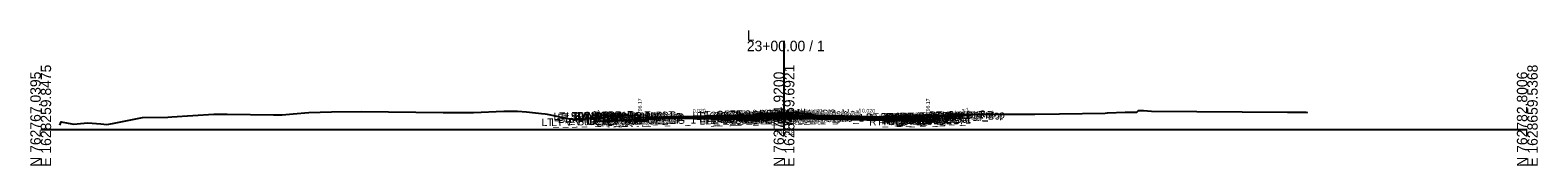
# Model space of a CAD drawing. Extents: x -26 to 4403, y -510 to 9556.
# Drawn here: x 997.2 to 1402.8, y 2990.3 to 3026.7 of the extents above; entities that cross this region are included whole.
import ezdxf

# ---------------------------------------------------------------- set-up
doc = ezdxf.new("R2010")
doc.units = 0
for name, color, linetype in [('Default', 7, 'Continuous'), ('Exist CMT Pavement', 7, 'Continuous'), ('Exist Cross Section Cell', 7, 'Continuous'), ('Exist XS Center Line Elevation Label', 7, 'Continuous'), ('Exist XS Ground Line', 7, 'Continuous'), ('Prop CMT Conc Surface', 7, 'Continuous'), ('Prop CMT Concrete Structures', 7, 'Continuous'), ('Prop CMT Pvmt Course 1', 7, 'Continuous'), ('Prop CMT Pvmt Course 1 CG', 7, 'Continuous'), ('Prop CMT Pvmt Course 2', 7, 'Continuous'), ('Prop CMT Pvmt Course 2 Wedge', 7, 'Continuous'), ('Prop CMT Pvmt Course 3', 7, 'Continuous'), ('Prop CMT Pvmt Course 3 Wedge', 7, 'Continuous'), ('Prop CMT Pvmt Surface', 7, 'Continuous'), ('Prop CMT Slope Grass', 7, 'Continuous'), ('Prop CMT Subgrade Earthwork', 7, 'Continuous'), ('Prop XS Hydro Elevations', 7, 'Continuous'), ('Prop XS SE Text', 7, 'Continuous'), ('Prop XS Side Slope Text', 7, 'Continuous'), ('Scratch_Level_0', 7, 'Continuous')]:
    doc.layers.add(name, color=color, linetype=linetype)

msp = doc.modelspace()

# ---------------------------------------------------------------- linework, layer by layer
at = {"layer": 'Exist CMT Pavement'}
msp.add_lwpolyline([(1163.23, 3002.78), (1167.94, 3002.97), (1171.5, 3003.11), (1176.96, 3002.96), (1190.67, 3002.61)], dxfattribs=at)
at = {"layer": 'Exist Cross Section Cell'}
for p, q in [((1200, 3000), (1200, 3023.91)), ((1000, 3000), (1200, 3000)), ((1200, 3000), (1400, 3000))]:
    msp.add_line(p, q, dxfattribs=at)
at = {"layer": 'Exist XS Ground Line'}
msp.add_lwpolyline([(1005.13, 3001.2), (1005.47, 3002.08), (1007.39, 3001.74), (1008.91, 3001.48), (1010.71, 3001.63), (1012.71, 3001.81), (1016.18, 3001.52), (1017.81, 3001.39), (1019.31, 3001.69), (1027.39, 3003.24), (1034.17, 3003.34), (1035.31, 3003.4), (1046.6, 3004.16), (1047.27, 3004.19), (1050.16, 3004.15), (1062.63, 3003.97), (1063.66, 3003.99), (1065.01, 3004.01), (1067.9, 3004.23), (1072.11, 3004.63), (1078.26, 3004.82), (1086.21, 3004.9), (1108.33, 3004.63), (1116.42, 3004.58), (1124.59, 3004.97), (1126.94, 3004.97), (1128.26, 3005), (1130.7, 3004.79), (1134.76, 3004.35), (1135.7, 3004.24), (1136.25, 3004.14), (1142.27, 3002.91), (1145.44, 3002.8), (1148.47, 3003.04), (1149.3, 3002.63), (1149.83, 3002.26), (1167.94, 3002.97), (1171.5, 3003.11), (1176.96, 3002.96), (1190.69, 3002.61), (1192.06, 3002.44), (1192.57, 3002.38), (1193.22, 3002.83), (1194.25, 3002.87), (1198.26, 3003.09), (1200, 3003.18), (1203.83, 3003.38), (1206.27, 3003.51), (1215.49, 3003.32), (1217.19, 3003.29), (1218.43, 3003.32), (1239.09, 3003.8), (1239.4, 3003.81), (1240.76, 3003.84), (1244.36, 3003.94), (1251.34, 3004.13), (1255.06, 3004.17), (1267.53, 3004.15), (1274.09, 3004.22), (1286.38, 3004.45), (1287.01, 3004.54), (1291.81, 3004.69), (1294.94, 3004.69), (1295.36, 3005.19), (1296.72, 3005.15), (1298.87, 3005), (1335.51, 3004.67), (1339.75, 3004.66), (1340.37, 3004.68), (1340.86, 3004.65)], dxfattribs=at)
at = {"layer": 'Prop CMT Conc Surface'}
for points in [[(1156.75, 3003.76), (1151.75, 3003.86)], [(1161.23, 3003.17), (1161.23, 3003.67), (1160.73, 3003.67)], [(1163.23, 3003.29), (1161.23, 3003.17)], [(1236.75, 3003.29), (1238.75, 3003.17)], [(1238.75, 3003.17), (1238.75, 3003.67), (1239.25, 3003.67)], [(1243.25, 3003.76), (1248.25, 3003.86)]]:
    msp.add_lwpolyline(points, dxfattribs=at)
at = {"layer": 'Prop CMT Concrete Structures'}
for p, q in [((1192.76, 3004.28), (1200, 3004.64)), ((1207.24, 3004.28), (1200, 3004.64)), ((1200, 3004.03), (1208, 3003.87))]:
    msp.add_line(p, q, dxfattribs=at)
for points in [[(1151.75, 3003.53), (1151.75, 3003.86)], [(1151.75, 3003.86), (1156.75, 3003.76)], [(1156.75, 3003.43), (1151.75, 3003.53)], [(1156.75, 3003.76), (1156.75, 3003.43)], [(1163.23, 3003.29), (1161.23, 3003.17), (1161.23, 3003.67), (1160.73, 3003.67)], [(1160.73, 3003.67), (1160.73, 3002.66), (1163.23, 3002.71)], [(1163.23, 3002.71), (1163.23, 3003.29)], [(1192.76, 3004.28), (1192.01, 3004.03), (1192, 3003.87)], [(1192, 3003.87), (1200, 3004.03)], [(1207.24, 3004.28), (1207.99, 3004.03), (1208, 3003.87)], [(1236.75, 3003.29), (1238.75, 3003.17), (1238.75, 3003.67), (1239.25, 3003.67)], [(1239.25, 3003.67), (1239.25, 3002.66), (1236.75, 3002.71)], [(1236.75, 3002.71), (1236.75, 3003.29)], [(1248.25, 3003.86), (1243.25, 3003.76)], [(1243.25, 3003.76), (1243.25, 3003.43)], [(1243.25, 3003.43), (1248.25, 3003.53)], [(1248.25, 3003.53), (1248.25, 3003.86)]]:
    msp.add_lwpolyline(points, dxfattribs=at)
at = {"layer": 'Prop CMT Pvmt Course 1'}
for points in [[(1200, 3004.03), (1163.23, 3003.29)], [(1163.23, 3003.04), (1190.67, 3003.59), (1200, 3003.78)], [(1163.23, 3003.29), (1163.23, 3003.04), (1163.23, 3003.04)], [(1200, 3003.78), (1200, 3004.03)], [(1200, 3004.03), (1236.75, 3003.29)], [(1236.75, 3003.04), (1200, 3003.78)], [(1208.75, 3003.6), (1208.75, 3003.6), (1208.75, 3003.6)], [(1236.75, 3003.29), (1236.75, 3003.04)]]:
    msp.add_lwpolyline(points, dxfattribs=at)
at = {"layer": 'Prop CMT Pvmt Course 1 CG'}
for points in [[(1163.23, 3002.71), (1160.23, 3002.65), (1159.89, 3002.31)], [(1159.89, 3002.31), (1163.23, 3002.38)], [(1163.23, 3002.38), (1163.23, 3002.71)], [(1200, 3003.11), (1191.25, 3002.94)], [(1200, 3003.11), (1200, 3003.45)], [(1206.41, 3002.98), (1208.75, 3002.94)], [(1236.75, 3002.71), (1239.75, 3002.65), (1240.09, 3002.31)], [(1236.75, 3002.38), (1236.75, 3002.71)], [(1240.09, 3002.31), (1236.75, 3002.38)]]:
    msp.add_lwpolyline(points, dxfattribs=at)
at = {"layer": 'Prop CMT Pvmt Course 2'}
for points in [[(1163.23, 3002.71), (1163.23, 3002.71), (1163.23, 3003.04), (1163.23, 3003.04)], [(1163.23, 3003.04), (1163.23, 3002.71)], [(1200, 3003.78), (1190.67, 3003.59)], [(1190.67, 3003.59), (1190.67, 3003.26)], [(1190.67, 3003.26), (1200, 3003.45)], [(1200, 3003.45), (1200, 3003.78)], [(1200, 3003.78), (1236.75, 3003.04)], [(1236.75, 3002.71), (1200, 3003.44)], [(1236.75, 3003.04), (1236.75, 3002.71)]]:
    msp.add_lwpolyline(points, dxfattribs=at)
at = {"layer": 'Prop CMT Pvmt Course 2 Wedge'}
for points in [[(1163.23, 3003.04), (1167.94, 3003.14), (1171.5, 3003.21), (1176.96, 3003.32), (1190.67, 3003.59)], [(1190.67, 3003.26), (1176.96, 3002.98), (1176.51, 3002.98), (1171.5, 3003.11), (1167.94, 3002.97), (1163.23, 3002.78)], [(1163.23, 3002.78), (1163.23, 3003.04)], [(1190.67, 3003.59), (1190.67, 3003.26)]]:
    msp.add_lwpolyline(points, dxfattribs=at)
at = {"layer": 'Prop CMT Pvmt Course 3'}
for points in [[(1163.23, 3002.71), (1163.23, 3002.71), (1163.23, 3002.38), (1163.23, 3002.38)], [(1163.23, 3002.38), (1163.23, 3002.71)], [(1200, 3003.45), (1190.67, 3003.26)], [(1190.67, 3003.26), (1190.67, 3002.92)], [(1190.67, 3002.92), (1191.25, 3002.94)], [(1200, 3003.11), (1200, 3003.45)], [(1200, 3003.44), (1236.75, 3002.71)], [(1236.75, 3002.38), (1200, 3003.11)], [(1236.75, 3002.71), (1236.75, 3002.38)]]:
    msp.add_lwpolyline(points, dxfattribs=at)
at = {"layer": 'Prop CMT Pvmt Course 3 Wedge'}
for points in [[(1176.52, 3002.97), (1176.96, 3002.98)], [(1190.67, 3002.61), (1176.96, 3002.96), (1176.52, 3002.97)], [(1176.96, 3002.98), (1190.67, 3003.26)], [(1190.67, 3003.26), (1190.67, 3002.61)]]:
    msp.add_lwpolyline(points, dxfattribs=at)
at = {"layer": 'Prop CMT Pvmt Surface'}
for points in [[(1200, 3004.03), (1163.23, 3003.29)], [(1200, 3004.03), (1236.75, 3003.29)]]:
    msp.add_lwpolyline(points, dxfattribs=at)
at = {"layer": 'Prop CMT Slope Grass'}
for points in [[(1160.73, 3003.67), (1151.25, 3003.86), (1148.59, 3002.98)], [(1239.25, 3003.67), (1248.75, 3003.86), (1249.4, 3004.08)]]:
    msp.add_lwpolyline(points, dxfattribs=at)
at = {"layer": 'Prop CMT Subgrade Earthwork'}
msp.add_line((1163.23, 3002.38), (1163.23, 3002.71), dxfattribs=at)
for points in [[(1163.23, 3002.38), (1159.89, 3002.31), (1158.48, 3003.72)], [(1163.23, 3002.38), (1163.23, 3002.38)], [(1163.23, 3002.38), (1163.23, 3002.38)], [(1191.25, 3002.94), (1190.67, 3002.92)], [(1190.67, 3002.92), (1190.67, 3002.61)], [(1200, 3003.11), (1191.25, 3002.94)], [(1200, 3003.11), (1200, 3003.11)], [(1200, 3003.11), (1208.75, 3002.94)], [(1208.75, 3002.94), (1236.75, 3002.38)], [(1208.75, 3002.94), (1208.75, 3002.94)], [(1208.75, 3002.94), (1208.75, 3002.94)], [(1236.75, 3002.38), (1240.09, 3002.31), (1241.5, 3003.72)], [(1236.75, 3002.38), (1236.75, 3002.38)]]:
    msp.add_lwpolyline(points, dxfattribs=at)

# ---------------------------------------------------------------- texts
at = {"layer": 'Default'}
msp.add_text('-', height=0.0001, dxfattribs=at).set_placement((1000, 3000))
at = {"layer": 'Exist Cross Section Cell'}
for s, p in [('L', (1190, 3023.91)), ('23+00.00 / 1', (1190, 3021.11))]:
    msp.add_text(s, height=2.8, dxfattribs=at).set_placement(p)
for s, p in [('N 762767.0395', (1000, 2990)), ('E 1628259.8475', (1002.8, 2990)), ('N 762774.9200', (1200, 2990)), ('E 1628459.6921', (1202.8, 2990)), ('N 762782.8006', (1400, 2990)), ('E 1628659.5368', (1402.8, 2990))]:
    msp.add_text(s, height=2.8, rotation=90, dxfattribs=at).set_placement(p)
at = {"layer": 'Exist XS Center Line Elevation Label'}
msp.add_text('796.18', height=1.2, dxfattribs=at).set_placement((1197.77, 2998.58))
at = {"layer": 'Prop XS Hydro Elevations'}
for p in [(1161.73, 3004.17), (1239.25, 3004.17)]:
    msp.add_text('796.17', height=1, rotation=90, dxfattribs=at).set_placement(p)
at = {"layer": 'Prop XS SE Text'}
for rotation, p in [(1.1448, (1175.47, 3004.54)), (358.8543, (1221.02, 3004.61))]:
    msp.add_text('0.020', height=1, rotation=rotation, dxfattribs=at).set_placement(p)
at = {"layer": 'Prop XS Side Slope Text'}
for rotation, p in [(18.441, (1148.93, 3003.88)), (18.3951, (1248.08, 3004.43))]:
    msp.add_text('3:1', height=1, rotation=rotation, dxfattribs=at).set_placement(p)
at = {"layer": 'Scratch_Level_0'}
for s, p in [('LT_PV_Sub_Tie_Out', (1134.79, 3000.96)), ('LT_PV_OEEOP_EG', (1137.39, 3001.01)), ('LT_SDWK_Out_Top', (1138.01, 3002.59)), ('LT_SDWK_Out_Bot', (1138.04, 3002.25)), ('LT_Sub_Trench_Out_DLT', (1139.07, 3002.33)), ('LT_Slope_Fill', (1139.13, 3001.79)), ('LT_CSLP_Pnt', (1141.45, 3002.67)), ('23+00.00', (1144.69, 3002.73)), ('LT_SDWK_In_Top', (1144.63, 3002.52)), ('LT_SDWK_In_Bot', (1144.66, 3002.19)), ('LT_CG1_Shelf_Out', (1146.8, 3001.38)), ('LT_CG_Top_Face', (1148.51, 3002.42)), ('LT_CG_Top_BOC', (1149.03, 3002.44)), ('LT_CG_Bot_BOC', (1149.06, 3001.43)), ('LT_Sub_OEOT_CG_1', (1149.47, 3001.1)), ('LT_CG_Top_Gut', (1149.49, 3001.94)), ('LT_Sub_OEOP', (1150.02, 3001.11)), ('LT_Sub_OEEOP', (1152.46, 3001.16)), ('LT_PV2_OEEOP', (1152.56, 3001.83)), ('LT_PV3_OEEOP', (1152.56, 3001.5)), ('LT_CG_Bot_IE', (1153.16, 3001.51)), ('LT_Sub_OEOT', (1153.33, 3001.18)), ('LT_PV2_OEOT', (1153.42, 3001.85)), ('LT_PV3_OEOT', (1153.42, 3001.51)), ('LT_PV1_OEOT', (1153.99, 3002.11)), ('23+00.00', (1154.26, 3002.54)), ('LT_CG_Top_Face_Med', (1175.39, 3002.7)), ('LT_CG_Top_Gut_Med', (1176.37, 3002.56)), ('LT_CG_Top_BOC_Med', (1177.18, 3002.97)), ('LT_CG_Bot_BOC_Med', (1177.21, 3001.99)), ('LT_PV_Sub_Tie_In', (1177.26, 3001.34)), ('LT_CG_Bot_IE_Med', (1177.34, 3001.99)), ('LT_Sub_IEOT_CG_1', (1178.14, 3001.67)), ('LT_PV_IEEOP_EG', (1178.88, 3001.37)), ('LT_Sub_IEEOP', (1180.55, 3001.72)), ('LT_PV2_IEEOP', (1180.64, 3002.39)), ('LT_PV3_IEEOP', (1180.64, 3002.06)), ('LT_CG1_Shelf_In', (1181.46, 3002.07)), ('LT_Sub_PGL', (1182.39, 3001.76)), ('LT_PV2_PGL', (1182.48, 3002.43)), ('LT_PV3_PGL', (1182.48, 3002.09)), ('LT_PV1_PGL', (1183.05, 3002.69)), ('LT_Sub_DLT_In', (1183.9, 3003.11)), ('LT_Sub_IEOP', (1184.36, 3001.8)), ('23+00.00', (1184.84, 3002.72)), ('23+00.00', (1186.88, 3003.17)), ('MD_Crown Point', (1187.09, 3003.17)), ('RT_CG_Top_Face_Med', (1191.35, 3002.7)), ('RT_CG_Top_BOC_Med', (1191.61, 3002.97)), ('RT_CG_Bot_BOC_Med', (1191.64, 3001.99)), ('RT_CG_Top_Gut_Med', (1192.32, 3002.55)), ('23+00.00', (1193.45, 3003.29)), ('RT_Sub_DLT_In', (1193.99, 3003.11)), ('RT_CG_Bot_IE_Med', (1194.79, 3001.99)), ('RT_CG1_Shelf_In', (1194.89, 3002.07)), ('RT_Sub_IEOT_CG_1', (1195.59, 3001.67)), ('RT_Sub_IEOP', (1197.14, 3001.8)), ('RT_Sub_OEEOP', (1197.94, 3001.72)), ('RT_PV2_OEEOP', (1198.03, 3002.39)), ('RT_PV3_OEEOP', (1198.03, 3002.06)), ('RT_Sub_IEEOP', (1198.58, 3001.73)), ('RT_PV2_IEEOP', (1198.68, 3002.4)), ('23+00.00', (1199.3, 3003.17)), ('RT_Sub_PGL', (1199.84, 3001.76)), ('RT_PV2_PGL', (1199.94, 3002.43)), ('RT_PV1_PGL', (1200.5, 3002.69)), ('23+00.00', (1201.58, 3002.72)), ('RT_Sub_Trench_Out_DLT', (1222.04, 3002.33)), ('23+00.00', (1222.14, 3002.31)), ('RT_Sub_OEOT_CG_1', (1222.95, 3001.1)), ('RT_CG_Top_Face', (1225.99, 3002.42)), ('RT_CG1_Shelf_Out', (1226.28, 3001.38)), ('RT_CG_Bot_IE', (1226.64, 3001.51)), ('RT_Sub_OEOT', (1226.8, 3001.18)), ('RT_PV2_OEOT', (1226.9, 3001.85)), ('RT_PV3_OEOT', (1226.9, 3001.51)), ('RT_CG_Top_Gut', (1226.96, 3001.94)), ('RT_PV1_OEOT', (1227.47, 3002.11)), ('RT_CG_Top_BOC', (1227.51, 3002.44)), ('RT_CG_Bot_BOC', (1227.54, 3001.43)), ('RT_Sub_OEOP', (1230.17, 3001.11)), ('23+00.00', (1230.73, 3002.11)), ('RT_SDWK_In_Top', (1231.08, 3002.52)), ('RT_SDWK_In_Bot', (1231.12, 3002.19)), ('23+00.00', (1234.02, 3002.57)), ('RT_SDWK_Out_Top', (1234.46, 3002.59)), ('RT_SDWK_Out_Bot', (1234.49, 3002.25)), ('RT_CSLP_Pnt', (1238.9, 3002.67)), ('RT_Slope_Cut', (1239.01, 3002.87)), ('23+00.00', (1241.77, 3002.73)), ('23+00.00', (1242.09, 3002.78))]:
    msp.add_text(s, height=2, rotation=1.1458, dxfattribs=at).set_placement(p)

doc.saveas('drawing.dxf')
